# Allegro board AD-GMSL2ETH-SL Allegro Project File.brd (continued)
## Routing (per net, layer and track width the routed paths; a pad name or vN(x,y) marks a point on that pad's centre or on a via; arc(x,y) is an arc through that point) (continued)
VBUS_USB_DEBUG: length 13.2
  BOTTOM w0.229: D2.C 79.66,6.49
  BOTTOM w0.356: P10.1 80.9,5.25 79.66,6.49 79.05,6.49 77.57,7.98 R181.1 77.12,9.58 76.89,9.81 76.89,11.16 77.23,11.49 C260.1 C259.1 U23.10
VCC_IN: length 11.6
  TOP w0.305: U10.19 33.82,87.95
  TOP w0.483: R211.1 v1(36.4,110.59)
  TOP w0.508: 35.85,99.21 TP5.1 ; TP5.1 35.85,100.74 ; TP5.1 35.09,99.97 ; TP5.1 36.61,99.97
  L5_PWR w0.508: v1(36.4,110.59) 34.7,110.59 31.6,107.49 v1(30.45,107.49)
  vias: v1(28.77,50.91) v1(28.77,50.15) v1(29.54,50.91) v1(29.54,50.15) v1(36.78,88.58) v1(36.78,87.82) v1(37.54,88.58) v1(37.54,87.82)
VCC_IN_1: length 8.5
  TOP w0.508: v1(31.5,117.2) 31.5,116.51
  L6_PWR w0.508: v1(31.5,117.2) 31.5,115.56 28.88,112.94 v1(28.88,110.46)
VCCOEN_PL_M2C: length 59
  TOP w0.203: v1(61.65,55.75) 60.23,55.75 56.41,51.94 R51.1 50.06,51.94 49.81,51.69 U26.3 ; P3.A20 v2(80.13,92.06)
  BOTTOM w0.203: v1(61.65,55.75) 61.09,56.32 61.09,70.51 80.13,89.56 v2(80.13,92.06)
VCCOEN_PS_M2C: length 60.4
  TOP w0.203: U26.1 50.15,50.39 50.39,50.15 R50.1 57.11,50.15 v1(61.65,54.69) ; P3.A19 v2(79.5,92.06)
  BOTTOM w0.203: v1(61.65,54.69) 60.67,55.66 60.67,70.97 79.5,89.8 v2(79.5,92.06)
VDD_ANALOG: length 25.6
  TOP w0.203: U3.31 v2(96.61,110.19)
  TOP w0.305: U3.6 v2(96.61,101.83) ; U3.27 98.61,109.98 v1(98.36,110.22) 98.11,109.97 U3.28 ; v1(110.16,105.51) 109.79,105.89 R89.2 ; v1(101.17,109.18) 100.76,108.77 U3.24 ; U3.19 101.06,106.27 v1(101.32,106.53) 101.08,106.77 U3.20 ; R139.2 108.9,108.49 v1(109.73,109.32) ; v1(101.12,102.86) 100.7,103.27 U3.13 ; U3.45 v1(92.21,104.77) ; U3.9 98.11,101.87 v1(98.36,101.61) 98.61,101.86 U3.10 ; U3.41 92.91,106.77 v1(92.66,107.03) 92.91,107.27 U3.40 ; R88.2 v1(108.15,102.51)
  TOP w0.33: C98.1 v1(70.91,103.73) U14.5 U14.1
  TOP w0.356: v1(101.32,106.53) C97.1 ; v1(101.17,109.18) C102.1 ; v1(101.12,102.86) C95.1 ; C99.1 v1(98.36,101.61) ; v1(92.21,104.77) C101.1
  BOTTOM w0.305: R57.2 v1(104.88,100.15)
  BOTTOM w0.356: v1(98.36,110.22) 98.78,110.22 C94.1
  BOTTOM w0.406: v1(92.66,107.03) 92.66,107.03 C157.1 ; v2(96.61,101.83) C158.1
  BOTTOM w0.508: R55.2 v1(105.46,110.89)
  vias: v1(116.84,98.56) v1(116.84,97.8) v1(117.6,98.56) v1(117.6,97.8)
VDDOCXO_3V3: length 7.3
  TOP w0.406: Y4.4 C117.1 111.03,112.6 C112.1 E2.2
1PPS_IN: length 104.1
  TOP w0.483: R185.1 v1(75.74,106.72)
  TOP w0.508: D6.3 v1(20.25,56.41)
  TOP w0.61: D6.3 RT19.1
  BOTTOM w0.508: v1(75.74,106.72) 75.74,109.09 72.52,112.32 57.23,112.32 53.9,108.99 53.9,82.07 28.24,56.41 v1(20.25,56.41)
A_CAPVDD: length 18.9
  TOP w0.508: 114,80.56 v1(113.16,80.56) C9.1 ; C16.1 112.46,83.6 v1(112.8,83.94) 113.45,84.59
  TOP w0.61: C7.1 119.02,84.99 118.59,85.42 114.28,85.42 113.45,84.59 ; C15.1 117.93,82.61 115.88,80.56 114,80.56
  TOP w0.762: C7.1 C15.1
  BOTTOM w0.305: U1.8 112.85,84.21 112.85,83.99 v1(112.8,83.94) ; v1(113.16,80.56) 113.21,80.51 113.21,80.27 U1.20
A_CFG0: length 3.1
  TOP w0.356: v2(112.85,87.73) 113.51,88.39 R145.1
  BOTTOM w0.203: U1.4 112.62,86.82 112.62,87.5 v2(112.85,87.73)
A_CKAN/CKDN/A3A/D1A: length 81.7
  TOP w0.108: v2(84.66,35.56) 84.49,35.74 81.33,35.74 77.43,31.84 77.43,29.6 P5.D16
  L8_SIG w0.102: v7(101.48,78.79) 101.48,78.54 96.25,73.31 96.25,70.21 96.14,70.11 94.97,70.11 94.69,69.83 94.69,69.38 94.97,69.1 96.17,69.1 96.27,68.99 96.27,68.79 96.17,68.69 94.97,68.69 94.69,68.41 94.69,67.95 94.97,67.67 96.14,67.67 96.25,67.57 96.25,67.37 96.14,67.27 94.97,67.27 94.69,66.99 94.69,66.53 94.97,66.25 96.14,66.25 96.25,66.15 96.25,65.95 96.14,65.84 94.97,65.84 94.69,65.56 94.69,65.11 94.97,64.83 96.14,64.83 96.25,64.73 96.25,64.52 96.14,64.42 94.97,64.42 94.69,64.14 94.69,63.69 94.97,63.41 96.14,63.41 96.41,63.14 96.41,61.4 83.67,48.66 83.67,36.09 84.02,35.74 84.49,35.74 v2(84.66,35.56)
  BOTTOM w0.108: v7(101.48,78.79) 101.73,78.79 102.66,79.72 104.96,79.72 105.69,80.45 105.69,80.59 U1.40
A_CKAP/CKDP/A2C/D0C: length 81.8
  TOP w0.108: v2(84.66,36.22) 84.48,36.04 81.2,36.04 77.12,31.97 77.12,29.6 P5.D15
  L8_SIG w0.102: v2(84.66,36.22) 84.48,36.04 84.15,36.04 83.97,36.22 83.97,37.53 84.07,37.63 84.15,37.63 84.25,37.74 84.25,37.94 84.15,38.04 84.07,38.04 83.97,38.14 83.97,48.53 96.71,61.27 96.71,63.27 96.27,63.71 95.09,63.71 94.99,63.81 94.99,64.02 95.09,64.12 96.27,64.12 96.55,64.4 96.55,64.85 96.27,65.13 95.09,65.13 94.99,65.23 94.99,65.44 95.09,65.54 96.27,65.54 96.55,65.82 96.55,66.28 96.27,66.56 95.09,66.56 94.99,66.66 94.99,66.86 95.09,66.96 96.27,66.96 96.55,67.24 96.55,67.7 96.27,67.98 95.09,67.98 94.99,68.08 94.99,68.28 95.09,68.38 96.3,68.38 96.58,68.66 96.58,69.12 96.3,69.4 95.09,69.4 94.99,69.5 94.99,69.7 95.09,69.81 96.27,69.81 96.55,70.09 96.55,73.18 101.69,78.33 v7(101.95,78.33)
  BOTTOM w0.108: U1.39 106.05,80.24 105.91,80.24 105.09,79.42 102.79,79.42 101.95,78.58 v7(101.95,78.33)
A_CKBN/CKEN/B1A/E1A: length 109.5
  TOP w0.108: v2(75.37,26.41) P5.B13
  L8_SIG w0.102: v2(75.37,26.41) 75.21,26.25 75.21,25.86 74.82,25.47 73.79,25.47 73.33,25.93 73.33,30.43 75.44,32.54 78.23,32.54 78.33,32.64 78.33,32.86 78.23,32.96 77.16,32.96 76.88,33.24 76.88,33.7 77.16,33.98 78.38,33.98 78.48,34.08 78.48,34.27 78.37,34.38 77.16,34.38 76.88,34.66 76.88,35.12 77.16,35.4 78.38,35.4 78.48,35.5 78.48,35.7 78.37,35.81 77.16,35.81 76.88,36.09 76.88,36.54 77.16,36.82 78.38,36.82 78.48,36.92 78.48,37.12 78.37,37.23 77.16,37.23 76.88,37.51 76.88,37.96 77.16,38.24 78.38,38.24 78.48,38.35 78.48,38.54 78.37,38.65 77.16,38.65 76.88,38.93 76.88,39.39 77.16,39.67 78.38,39.67 78.48,39.77 78.48,39.96 78.37,40.07 77.16,40.07 76.88,40.35 76.88,40.81 77.16,41.09 78.38,41.09 78.48,41.19 78.48,41.39 78.37,41.5 77.16,41.5 76.88,41.78 76.88,42.23 77.16,42.51 78.38,42.51 78.48,42.61 78.48,42.81 78.37,42.92 77.16,42.92 76.88,43.2 76.88,43.65 77.16,43.93 78.38,43.93 78.48,44.04 78.48,44.23 78.37,44.34 77.16,44.34 76.88,44.62 76.88,45.08 77.16,45.36 78.38,45.36 78.48,45.46 78.48,45.65 78.37,45.76 77.26,45.76 76.98,46.04 76.98,46.49 77.27,46.78 78.38,46.78 78.48,46.88 78.48,63.23 100.71,85.46 103.25,85.46 v7(103.43,85.64)
  BOTTOM w0.108: v7(103.43,85.64) 103.6,85.46 104.35,85.46 105.61,84.19 105.75,84.19 U1.46
A_CKBP/CKEP/B0C/E0C: length 109.3
  TOP w0.108: v2(74.74,26.41) P5.B12
  L8_SIG w0.102: v2(74.74,26.41) 74.9,26.25 74.9,25.99 74.69,25.78 73.91,25.78 73.63,26.06 73.63,27.21 73.73,27.31 74.01,27.31 74.11,27.41 74.11,27.61 74.01,27.71 73.73,27.71 73.63,27.82 73.63,28.02 73.73,28.12 74.01,28.12 74.11,28.22 74.11,28.43 74.01,28.53 73.73,28.53 73.63,28.63 73.63,30.3 75.56,32.23 78.35,32.23 78.63,32.51 78.63,32.99 78.35,33.27 77.29,33.27 77.19,33.37 77.19,33.57 77.29,33.67 78.51,33.67 78.78,33.95 78.78,34.4 78.5,34.69 77.29,34.69 77.19,34.79 77.19,34.99 77.29,35.1 78.51,35.1 78.78,35.37 78.78,35.82 78.5,36.11 77.29,36.11 77.19,36.21 77.19,36.42 77.29,36.52 78.51,36.52 78.78,36.79 78.78,37.25 78.5,37.53 77.29,37.53 77.19,37.64 77.19,37.84 77.29,37.94 78.51,37.94 78.78,38.21 78.78,38.67 78.5,38.96 77.29,38.96 77.19,39.06 77.19,39.26 77.29,39.36 78.51,39.36 78.78,39.63 78.78,40.09 78.5,40.38 77.29,40.38 77.19,40.48 77.19,40.68 77.29,40.78 78.51,40.78 78.78,41.06 78.78,41.51 78.5,41.8 77.29,41.8 77.19,41.9 77.19,42.11 77.29,42.21 78.51,42.21 78.78,42.48 78.78,42.94 78.5,43.22 77.29,43.22 77.19,43.32 77.19,43.53 77.29,43.63 78.51,43.63 78.78,43.9 78.78,44.36 78.5,44.65 77.29,44.65 77.19,44.75 77.19,44.95 77.29,45.05 78.51,45.05 78.78,45.32 78.78,45.78 78.5,46.07 77.39,46.07 77.29,46.17 77.29,46.36 77.4,46.47 78.5,46.47 78.78,46.75 78.78,63.1 100.84,85.16 103.25,85.16 v7(103.43,84.98)
  BOTTOM w0.108: U1.45 105.4,83.84 105.4,83.98 104.22,85.15 103.6,85.15 v7(103.43,84.98)
A_DA0N/DC0N/A0B/C0B: length 84.6
  TOP w0.108: v2(91.81,36.18) 91.63,36.36 88.37,36.36 87.03,37.7 80.41,37.7 75.53,32.82 75.53,29.6 P5.D13
  L8_SIG w0.102: v7(107.21,77.45) 107.02,77.26 106.31,77.26 105.7,76.66 105.7,67.25 105.98,66.97 107.63,66.97 107.73,66.86 107.73,66.66 107.63,66.56 105.98,66.56 105.7,66.28 105.7,65.82 105.98,65.54 107.63,65.54 107.73,65.44 107.73,65.24 107.63,65.14 105.98,65.14 105.7,64.86 105.7,64.4 105.98,64.12 107.63,64.12 107.73,64.02 107.73,63.82 107.63,63.71 105.98,63.71 105.7,63.43 105.7,59.48 90.65,44.43 90.65,36.97 91.26,36.36 91.63,36.36 91.63,36.36 v2(91.81,36.18)
  BOTTOM w0.108: v7(107.21,77.45) 107.38,77.27 108.16,77.27 108.53,77.63 108.53,77.77 U1.32
A_DA0P/DC0P/A0A/C0A: length 85.1
  TOP w0.108: P5.D12 75.22,29.6 75.22,32.94 80.28,38.01 87.16,38.01 88.5,36.66 91.63,36.66 v2(91.81,36.84)
  L8_SIG w0.102: v7(107.21,76.78) 107.03,76.96 106.43,76.96 106.01,76.53 106.01,67.37 106.11,67.27 107.76,67.27 108.04,66.99 108.04,66.53 107.76,66.25 106.11,66.25 106.01,66.15 106.01,65.95 106.11,65.85 107.76,65.85 108.04,65.57 108.04,65.11 107.76,64.83 106.11,64.83 106.01,64.73 106.01,64.53 106.11,64.43 107.76,64.43 108.04,64.15 108.04,63.69 107.76,63.41 106.11,63.41 106.01,63.31 106.01,59.35 90.95,44.3 90.95,39.12 91.06,39.01 91.35,39.01 91.45,38.91 91.45,38.71 91.35,38.61 91.06,38.61 90.95,38.51 90.95,37.1 91.39,36.66 91.63,36.66 v2(91.81,36.84)
  BOTTOM w0.108: U1.31 108.88,77.42 108.74,77.42 108.29,76.96 107.38,76.96 v7(107.21,76.78)
A_DA1N/DC1N/A1C/C1C: length 76
  TOP w0.108: P5.C18 v2(79.18,28.95)
  L8_SIG w0.102: v2(79.18,28.95) 79.02,28.79 79.02,27.77 79.72,27.07 79.72,25.61 80.04,25.29 80.18,25.29 80.33,25.44 80.49,25.44 80.63,25.31 80.63,25.16 80.47,25 80.47,24.86 80.9,24.42 86.5,24.42 88.26,26.19 88.26,46.24 103.06,61.03 103.06,74.99 103.98,75.92 v7(103.98,76.17)
  BOTTOM w0.108: v7(103.98,76.17) 104.23,76.17 107.11,79.05 107.11,79.18 U1.36
A_DA1P/DC1P/A1B/C1B: length 76.2
  TOP w0.108: P5.C17 v2(78.55,28.95)
  L8_SIG w0.102: v7(104.45,75.7) 104.2,75.7 103.36,74.86 103.36,60.9 88.57,46.11 88.57,26.06 86.63,24.12 80.78,24.12 79.41,25.48 79.41,26.95 78.71,27.65 78.71,28.78 v2(78.55,28.95)
  BOTTOM w0.108: v7(104.45,75.7) 104.45,75.95 107.31,78.82 107.45,78.82 U1.35
A_DA2N/DD0N/A2B/D0B: length 77
  TOP w0.108: v2(82.99,27.37) P5.B25
  L8_SIG w0.102: v7(103.56,78.32) 103.56,78.07 99.78,74.29 99.78,60.64 98.29,59.15 98.15,59.15 97.62,59.68 97.22,59.68 96.9,59.36 96.9,58.96 97.43,58.43 97.43,58.29 97.29,58.14 97.14,58.14 96.61,58.68 96.21,58.68 95.89,58.36 95.89,57.96 96.43,57.42 96.43,57.28 96.28,57.14 96.14,57.14 95.6,57.67 95.21,57.67 94.89,57.35 94.89,56.95 95.42,56.42 95.42,56.28 95.28,56.13 95.13,56.13 94.6,56.67 94.2,56.67 93.88,56.34 93.88,55.95 94.41,55.41 94.41,55.27 94.27,55.13 94.13,55.13 93.59,55.66 93.2,55.66 92.87,55.34 92.87,54.94 93.41,54.41 93.41,54.26 93.26,54.12 93.12,54.12 92.59,54.65 92.19,54.65 91.87,54.33 91.87,53.94 92.4,53.4 92.4,53.26 86.36,47.22 86.36,28.7 84.86,27.2 84.32,27.2 84.22,27.3 84.22,27.51 84.11,27.61 83.91,27.61 83.81,27.51 83.81,27.3 83.71,27.2 83.17,27.2 v2(82.99,27.37)
  BOTTOM w0.108: U1.38 106.4,79.89 106.4,79.75 105.37,78.72 104.21,78.72 103.81,78.32 v7(103.56,78.32)
A_DA2P/DD0P/A2A/D0A: length 76.9
  TOP w0.108: v2(82.99,26.41) P5.B24
  L8_SIG w0.102: v2(82.99,26.41) 82.99,26.72 83.17,26.89 84.98,26.89 86.66,28.57 86.66,47.09 92.71,53.13 92.71,53.53 92.17,54.06 92.17,54.21 92.32,54.35 92.46,54.35 92.99,53.81 93.39,53.81 93.71,54.14 93.71,54.53 93.18,55.07 93.18,55.21 93.32,55.35 93.47,55.35 94,54.82 94.4,54.82 94.72,55.14 94.72,55.54 94.18,56.07 94.18,56.22 94.33,56.36 94.47,56.36 95.01,55.83 95.4,55.83 95.72,56.15 95.72,56.54 95.19,57.08 95.19,57.22 95.33,57.37 95.48,57.37 96.01,56.83 96.41,56.83 96.73,57.15 96.73,57.55 96.2,58.09 96.2,58.23 96.34,58.37 96.48,58.37 97.02,57.84 97.41,57.84 97.74,58.16 97.74,58.56 97.2,59.09 97.2,59.23 97.35,59.38 97.49,59.38 98.02,58.84 98.42,58.84 100.08,60.51 100.08,74.16 103.77,77.85 v7(104.02,77.85)
  BOTTOM w0.108: v7(104.02,77.85) 104.02,78.1 104.34,78.41 105.5,78.41 106.61,79.53 106.75,79.53 U1.37
A_DA3N/DD1N/A3C/D1C: length 78.3
  TOP w0.108: v2(83.49,33.7) 83.31,33.88 82.71,33.88 81.24,32.41 81.24,29.6 P5.D22
  L8_SIG w0.102: v2(83.49,33.7) 83.31,33.88 82.84,33.88 81.94,34.78 81.94,51 83.43,52.5 83.83,52.5 84.55,51.79 84.69,51.79 84.83,51.93 84.83,52.07 84.12,52.79 84.12,53.19 84.44,53.51 84.84,53.51 85.55,52.79 85.7,52.79 85.84,52.94 85.84,53.08 85.12,53.79 85.12,54.19 85.45,54.51 85.84,54.51 86.56,53.8 86.7,53.8 86.85,53.94 86.85,54.08 86.13,54.8 86.13,55.2 86.45,55.52 86.85,55.52 87.56,54.8 87.71,54.8 87.85,54.95 87.85,55.09 87.14,55.81 87.14,56.2 87.46,56.53 87.85,56.53 88.57,55.81 88.71,55.81 88.86,55.95 88.86,56.1 88.29,56.67 88.29,57.06 92.79,61.56 92.79,72.53 101.08,80.82 101.64,80.82 v7(101.82,81)
  BOTTOM w0.108: v7(101.82,81) 101.99,80.82 104.64,80.82 104.98,81.16 104.98,81.29 U1.42
A_DA3P/DD1P/A3B/D1B: length 78.5
  TOP w0.108: v2(83.49,34.36) 83.31,34.19 82.59,34.19 80.93,32.53 80.93,29.6 P5.D21
  L8_SIG w0.102: v7(101.82,80.34) 101.64,80.52 101.21,80.52 93.09,72.4 93.09,61.44 88.59,56.94 88.59,56.79 89.16,56.22 89.16,55.83 88.84,55.5 88.44,55.5 87.73,56.22 87.58,56.22 87.44,56.08 87.44,55.93 88.16,55.22 88.16,54.82 87.83,54.5 87.44,54.5 86.72,55.21 86.58,55.21 86.43,55.07 86.43,54.93 87.15,54.21 87.15,53.82 86.83,53.49 86.43,53.49 85.72,54.21 85.57,54.21 85.43,54.06 85.43,53.92 86.14,53.21 86.14,52.81 85.82,52.49 85.43,52.49 84.71,53.2 84.57,53.2 84.42,53.06 84.42,52.92 85.14,52.2 85.14,51.8 84.82,51.48 84.42,51.48 83.7,52.2 83.56,52.2 82.24,50.88 82.24,35.82 82.34,35.72 82.49,35.72 82.59,35.62 82.59,35.41 82.49,35.31 82.34,35.31 82.24,35.21 82.24,34.91 82.96,34.19 83.31,34.19 v2(83.49,34.36)
  BOTTOM w0.108: U1.41 105.32,80.92 105.18,80.92 104.77,80.52 101.99,80.52 v7(101.82,80.34)
A_DB0N/DE0N/B0B/E0B: length 108.8
  TOP w0.108: P5.B22 v2(81.09,27.37)
  L8_SIG w0.102: v2(81.09,27.37) 81.36,27.37 81.58,27.59 81.58,30.54 80.21,31.91 80.21,32.58 80.11,32.68 80.03,32.68 79.93,32.78 79.93,32.99 80.03,33.09 80.11,33.09 80.21,33.19 80.21,53.69 80.49,53.97 82.41,53.97 82.51,54.08 82.51,54.28 82.41,54.38 80.49,54.38 80.21,54.66 80.21,55.12 80.49,55.4 82.41,55.4 82.51,55.5 82.51,55.7 82.41,55.8 80.49,55.8 80.21,56.08 80.21,56.54 80.49,56.82 82.41,56.82 82.51,56.92 82.51,57.12 82.41,57.23 80.49,57.23 80.21,57.51 80.21,57.96 80.49,58.24 82.41,58.24 82.51,58.34 82.51,58.55 82.41,58.65 80.54,58.65 80.26,58.93 80.26,59.4 80.54,59.68 81.86,59.68 81.97,59.78 81.97,60.97 82.86,61.87 82.86,62.01 82.19,62.68 82.19,63.07 82.51,63.4 82.91,63.4 83.7,62.61 83.84,62.61 83.98,62.75 83.98,62.89 83.2,63.68 83.2,64.08 83.52,64.4 83.91,64.4 84.7,63.61 84.85,63.61 84.99,63.76 84.99,63.9 84.2,64.69 84.2,65.09 84.52,65.41 84.92,65.41 85.71,64.62 85.85,64.62 86,64.76 86,64.91 85.21,65.7 85.21,66.09 85.53,66.41 85.93,66.41 86.95,65.39 87.1,65.39 87.24,65.53 87.24,65.67 86.21,66.7 86.21,67.1 86.54,67.42 86.96,67.42 88.03,66.35 88.18,66.35 88.31,66.48 88.31,66.62 87.22,67.71 87.22,68.1 87.54,68.43 87.94,68.43 88.73,67.64 88.87,67.64 89.01,67.78 89.01,67.92 88.22,68.71 88.22,69.11 88.55,69.43 88.94,69.43 89.73,68.64 89.88,68.64 90.09,68.85 90.09,68.99 89.42,69.67 89.42,71.65 101.42,83.65 102.53,83.65 v7(102.7,83.83)
  BOTTOM w0.108: U1.44 105.3,83.24 105.16,83.24 104.74,83.65 102.88,83.65 v7(102.7,83.83)
A_DB0P/DE0P/B0A/E0A: length 108.6
  TOP w0.108: v2(81.09,26.41) P5.B21
  L8_SIG w0.102: v2(81.09,26.41) 81.09,26.41 81.09,26.67 81.88,27.46 81.88,30.66 80.52,32.03 80.52,53.57 80.62,53.67 82.54,53.67 82.82,53.95 82.82,54.41 82.54,54.69 80.62,54.69 80.52,54.79 80.52,54.99 80.62,55.09 82.54,55.09 82.82,55.37 82.82,55.83 82.54,56.11 80.62,56.11 80.52,56.21 80.52,56.41 80.62,56.51 82.54,56.51 82.82,56.79 82.82,57.25 82.54,57.53 80.62,57.53 80.52,57.63 80.52,57.84 80.62,57.94 82.54,57.94 82.82,58.22 82.82,58.67 82.54,58.95 80.67,58.95 80.57,59.05 80.57,59.27 80.67,59.38 81.99,59.38 82.27,59.66 82.27,60.85 83.16,61.74 83.16,62.14 82.49,62.8 82.49,62.95 82.64,63.09 82.78,63.09 83.57,62.3 83.97,62.3 84.29,62.62 84.29,63.02 83.5,63.81 83.5,63.95 83.64,64.1 83.79,64.1 84.58,63.31 84.97,63.31 85.3,63.63 85.3,64.03 84.51,64.82 84.51,64.96 84.65,65.1 84.79,65.1 85.58,64.31 85.98,64.31 86.3,64.64 86.3,65.03 85.51,65.82 85.51,65.96 85.66,66.11 85.8,66.11 86.83,65.08 87.22,65.08 87.55,65.4 87.55,65.8 86.52,66.83 86.52,66.97 86.66,67.11 86.84,67.11 87.91,66.04 88.3,66.04 88.61,66.35 88.61,66.75 87.52,67.83 87.52,67.98 87.67,68.12 87.81,68.12 88.6,67.33 89,67.33 89.32,67.65 89.32,68.05 88.53,68.84 88.53,68.98 88.67,69.13 88.82,69.13 89.61,68.34 90.01,68.34 90.4,68.72 90.4,69.12 89.72,69.79 89.72,71.53 101.54,83.35 102.53,83.35 v7(102.7,83.17)
  BOTTOM w0.108: v7(102.7,83.17) 102.88,83.35 104.61,83.35 104.94,83.02 104.94,82.88 U1.43
A_DB1N/DE1N/B1C/E1C: length 113.2
  TOP w0.108: P5.A18 78.7,25.77 78.7,23.79 78.14,23.23 76.56,23.23 75.71,24.08 75.34,24.08 75.18,23.93 v2(75.14,23.93)
  L8_SIG w0.102: v7(102.44,87.4) 102.26,87.22 99.6,87.22 74.8,62.42 74.8,60.36 75.09,60.07 76.42,60.07 76.53,59.96 76.53,59.76 76.42,59.66 75.12,59.66 74.84,59.38 74.84,58.92 75.12,58.64 76.42,58.64 76.53,58.54 76.53,58.34 76.42,58.24 75.32,58.24 75.04,57.96 75.04,57.5 75.32,57.22 76.42,57.22 76.53,57.12 76.53,56.92 76.42,56.81 75.32,56.81 75.04,56.53 75.04,56.08 75.32,55.8 76.42,55.8 76.53,55.7 76.53,55.49 76.42,55.39 75.32,55.39 75.04,55.11 75.04,54.66 75.32,54.38 76.42,54.38 76.53,54.27 76.53,54.07 76.42,53.97 75.32,53.97 75.04,53.69 75.04,53.23 75.32,52.95 76.42,52.95 76.53,52.85 76.53,52.65 76.42,52.55 75.32,52.55 75.04,52.27 75.04,51.81 75.32,51.53 76.42,51.53 76.53,51.43 76.53,51.23 76.42,51.13 75.32,51.13 75.04,50.84 75.04,50.39 75.32,50.11 76.42,50.11 76.53,50.01 76.53,49.8 76.42,49.7 75.32,49.7 75.04,49.42 75.04,35.09 72.05,32.1 72.05,25.39 73.35,24.08 74.73,24.08 74.88,23.93 v2(75.14,23.93)
  BOTTOM w0.108: v7(102.44,87.4) 102.62,87.22 104,87.22 106.32,84.9 106.46,84.9 U1.48
A_DB1P/DE1P/B1B/E1B: length 113
  TOP w0.108: v2(75.14,24.54) 75.18,24.54 75.34,24.39 75.84,24.39 76.69,23.54 78.01,23.54 78.4,23.92 78.4,25.76 P5.A17
  L8_SIG w0.102: v2(75.14,24.54) 74.88,24.54 74.73,24.39 73.48,24.39 72.36,25.51 72.36,31.98 72.95,32.57 73.09,32.57 73.33,32.34 73.47,32.34 73.62,32.48 73.62,32.62 73.38,32.86 73.38,33 73.52,33.15 73.67,33.15 73.88,32.93 74.02,32.93 74.17,33.08 74.17,33.22 73.96,33.43 73.96,33.58 75.34,34.96 75.34,49.3 75.44,49.4 76.55,49.4 76.83,49.68 76.83,50.13 76.55,50.41 75.44,50.41 75.34,50.52 75.34,50.72 75.44,50.82 76.55,50.82 76.83,51.1 76.83,51.56 76.55,51.84 75.44,51.84 75.34,51.94 75.34,52.14 75.44,52.24 76.55,52.24 76.83,52.52 76.83,52.98 76.55,53.26 75.44,53.26 75.34,53.36 75.34,53.56 75.44,53.67 76.55,53.67 76.83,53.95 76.83,54.4 76.55,54.68 75.44,54.68 75.34,54.78 75.34,54.99 75.44,55.09 76.55,55.09 76.83,55.37 76.83,55.82 76.55,56.1 75.44,56.1 75.34,56.21 75.34,56.41 75.44,56.51 76.55,56.51 76.83,56.79 76.83,57.25 76.55,57.53 75.44,57.53 75.34,57.63 75.34,57.83 75.44,57.93 76.55,57.93 76.83,58.21 76.83,58.67 76.55,58.95 75.24,58.95 75.14,59.05 75.14,59.25 75.24,59.35 76.55,59.35 76.83,59.63 76.83,60.09 76.55,60.37 75.22,60.37 75.1,60.49 75.1,62.29 99.73,86.92 102.26,86.92 v7(102.44,86.74)
  BOTTOM w0.108: v7(102.44,86.74) 102.62,86.91 103.87,86.91 106.1,84.69 106.1,84.55 U1.47
A_DB2N/DF0N/B2B/F0B: length 109.4
  TOP w0.108: P5.C21 v2(80.45,28.95)
  L8_SIG w0.102: v2(80.45,28.95) 80.64,29.14 80.64,29.85 79.91,30.58 76.03,30.58 75.55,30.1 75.55,28.34 77.03,26.87 77.03,23.94 75.73,22.65 72.84,22.65 70.78,24.7 70.78,33.3 71.22,33.74 71.22,33.88 71.1,34 71.1,34.14 71.25,34.29 71.39,34.29 71.51,34.17 71.65,34.17 72.88,35.4 72.88,37.54 72.16,38.26 72.16,62.54 98.58,88.96 103.68,88.96 104.08,88.56 v7(104.33,88.56)
  BOTTOM w0.108: U1.50 107.16,85.61 107.03,85.61 104.33,88.31 v7(104.33,88.56)
A_DB2P/DF0P/B2A/F0A: length 109.2
  TOP w0.108: v2(80.45,27.99) P5.C20
  L8_SIG w0.102: v7(103.86,88.09) 103.86,88.35 103.56,88.65 98.7,88.65 72.46,62.42 72.46,38.39 73.19,37.67 73.19,35.27 71.08,33.17 71.08,24.83 72.96,22.95 75.6,22.95 76.72,24.07 76.72,26.74 75.25,28.21 75.25,30.23 75.91,30.89 80.03,30.89 80.95,29.97 80.95,28.87 80.45,28.37 v2(80.45,27.99)
  BOTTOM w0.108: v7(103.86,88.09) 104.11,88.09 106.81,85.4 106.81,85.26 U1.49
A_DB3N/DF1N/B3C/F1C: length 109.2
  TOP w0.108: P5.C15 v2(77.28,28.95)
  L8_SIG w0.102: v7(106.2,89.22) 105.94,89.22 104.59,90.57 97.52,90.57 69.49,62.54 69.49,24.06 71.83,21.72 76.78,21.72 78.64,23.57 78.64,26.68 77.11,28.21 77.11,28.79 v2(77.28,28.95)
  BOTTOM w0.108: U1.54 108.87,86.74 108.73,86.74 108.37,87.1 108.06,87.1 106.2,88.97 v7(106.2,89.22)
A_DB3P/DF1P/B3B/F1B: length 109.2
  TOP w0.108: P5.C14 v2(76.64,28.95)
  L8_SIG w0.102: v2(76.64,28.95) 76.81,28.79 76.81,28.08 78.34,26.55 78.34,25.56 78.23,25.46 77.88,25.46 77.78,25.36 77.78,25.16 77.88,25.05 78.23,25.05 78.34,24.95 78.34,24.75 78.23,24.65 77.88,24.65 77.78,24.55 77.78,24.34 77.88,24.24 78.23,24.24 78.34,24.14 78.34,23.7 76.66,22.02 71.96,22.02 69.8,24.18 69.8,62.42 97.64,90.27 104.47,90.27 105.73,89 v7(105.73,88.75)
  BOTTOM w0.108: v7(105.73,88.75) 105.98,88.75 107.94,86.8 108.24,86.8 108.51,86.52 108.51,86.38 U1.53
A_GMSL-PWDNB: length 78.1
  TOP w0.203: v2(95.06,27.37) P5.B44
  TOP w0.356: v1(112.26,90.73) 113.51,90.73 R154.1
  L3_SIG w0.356: v2(115.04,84.28) 115.04,87.96 v1(112.26,90.73)
  L8_SIG w0.203: v2(95.06,27.37) 93.51,28.92 93.51,32.04 95.48,34.01 95.48,44.92 110.49,59.93 110.49,68.63 116.48,74.62 116.48,82.07 115.04,83.52 v2(115.04,84.28)
  BOTTOM w0.203: U1.11 v2(115.04,84.28)
A_MFP0/LMN0/FSYNC: length 81.3
  TOP w0.203: v2(96.96,25.45) P5.A46
  L8_SIG w0.203: v2(111.51,89) 111.79,89.28 113.41,89.28 114.58,88.11 114.58,83.39 116.08,81.89 116.08,74.79 110.08,68.8 110.08,60.1 95.07,45.09 95.07,34.18 93.1,32.21 93.1,28.54 96.19,25.45 v2(96.96,25.45)
  BOTTOM w0.203: v2(111.51,89) 111.25,88.75 111.25,87.57 U1.1
A_MFP1/LMN1/VS0/DE0/HS0: length 81.8
  TOP w0.203: v2(97.6,25.45) P5.A47
  L8_SIG w0.203: v2(111.96,88.57) 112.24,88.85 113.18,88.85 114.15,87.88 114.15,83.24 115.67,81.71 115.67,74.98 109.66,68.97 109.66,60.26 94.67,45.26 94.67,34.35 92.69,32.37 92.69,28.36 96.08,24.97 97.41,24.97 97.6,25.16 v2(97.6,25.45)
  BOTTOM w0.203: v2(111.96,88.57) 111.71,88.32 111.71,87.32 U1.2
A_MFP2/LMN2: length 82.1
  TOP w0.203: v2(98.23,25.45) P5.A48
  L8_SIG w0.203: v2(112.4,88.14) 112.65,88.39 113.06,88.39 113.73,87.72 113.73,83.06 115.27,81.53 115.27,75.15 109.26,69.14 109.26,60.42 94.26,45.43 94.26,34.52 92.28,32.54 92.28,28.19 95.91,24.56 97.69,24.56 98.23,25.11 v2(98.23,25.45)
  BOTTOM w0.203: v2(112.4,88.14) 112.17,87.91 112.17,87.07 U1.3
A_MFP3/LMN3/VS1/DE1/HS1: length 69.3
  TOP w0.203: v2(95.69,27.37) P5.B45
  L8_SIG w0.203: v2(95.69,27.37) 95.69,27.4 93.91,29.17 93.91,31.87 95.88,33.84 95.88,44.75 110.9,59.77 110.9,68.46 116.89,74.45 116.89,82.24 115.57,83.56 v2(115.57,84.1)
  BOTTOM w0.203: v2(115.57,84.1) U1.12
A_MFP4/LOCK: length 70.7
  TOP w0.203: v2(96.33,27.37) P5.B46
  L8_SIG w0.203: v2(116.53,84.36) 116.13,83.96 116.13,83.58 117.3,82.41 117.3,74.29 111.3,68.29 111.3,59.6 96.29,44.59 96.29,33.67 94.32,31.7 94.32,29.39 96.33,27.38 v2(96.33,27.37)
  BOTTOM w0.203: v2(116.53,84.36) U1.13
A_MFP5/ERRB: length 69.9
  TOP w0.203: v2(95.7,29) 96.3,29 P5.C46
  L8_SIG w0.203: v2(116.62,83.74) 118.55,81.8 118.55,74.54 118.08,74.07 118.08,70.08 117.4,69.39 114.13,69.39 112.55,67.81 112.55,59.12 97.51,44.08 97.51,32.26 96.24,30.99 96.24,29.54 v2(95.7,29)
  BOTTOM w0.203: v2(116.62,83.74) U1.14
A_MFP6/CFG1: length 69.8
  TOP w0.203: P5.C47 97.28,28.12 97.05,27.89 v2(96.61,27.89)
  TOP w0.305: R151.1 119.51,71.18 v2(119.51,70.03)
  L8_SIG w0.203: v2(96.61,27.89) 96.61,30.77 97.92,32.08 97.92,43.91 112.95,58.95 112.95,67.64 114.3,68.99 117.58,68.99 118.59,70 119.47,70 v2(119.51,70.03)
  BOTTOM w0.203: v2(119.51,70.03) 118.88,69.41 117.25,69.41 113.23,73.43 113.23,76.72 113.06,76.89 113.06,76.89 112.87,77.08 112.87,77.08 111.87,78.08 U1.25
A_MFP7: length 52.5
  TOP w0.203: v2(95.69,29.91) P5.D45 ; R125.2 v2(117.57,70.31)
  L8_SIG w0.203: v2(95.69,29.91) 95.69,31.91 97.1,33.32 97.1,44.25 112.12,59.26 112.12,67.95 113.96,69.8 117.06,69.8 v2(117.57,70.31)
A_MFP7/SDA1_RX1: length 12.1
  TOP w0.203: v2(112.6,75.34) 112.6,74.85 116.67,70.78 R125.1 R167.2 116.67,68.38 116.56,68.27 U20.2
  BOTTOM w0.203: U1.26 112.6,76.64 v2(112.6,75.34)
A_MFP8: length 50.6
  TOP w0.203: v2(95.06,29.91) P5.D44 ; R126.2 v2(115.04,70.31)
  L8_SIG w0.203: v2(95.06,29.91) 95.06,31.85 96.7,33.49 96.7,44.42 111.71,59.43 111.71,68.12 113.89,70.31 v2(115.04,70.31)
A_MFP8/SCL1_TX1: length 11.6
  TOP w0.203: v2(111.99,75.34) 111.99,74.68 115.94,70.73 R126.1 R166.2 115.94,68.38 116.06,68.27 U20.3
  BOTTOM w0.203: v2(111.99,75.34) 111.99,76.54 U1.27
A_SCL: length 46.6
  TOP w0.203: U19.8 138.85,59.12 v2(139.04,59.31) 140.93,59.31 R129.2
  L3_SIG w0.203: v2(139.04,59.31) 139.55,58.8 139.55,58.23 139.25,57.94 134.63,57.94 133.78,58.79 133.78,60.66 130.33,64.11 126.62,64.11 124.74,65.99 124.74,71.76 120.64,75.87 111.06,75.87 v2(111.05,75.87)
  BOTTOM w0.203: U1.29 v2(111.05,75.87)
A_SDA: length 43.6
  TOP w0.203: U19.7 138.86,58.62 v2(139.04,58.45) R134.2
  L3_SIG w0.203: v2(111.5,76.32) 121.06,76.32 125.28,72.1 125.28,66.13 126.85,64.57 130.52,64.57 134.24,60.85 134.24,58.98 134.77,58.45 v2(139.04,58.45)
  BOTTOM w0.203: U1.28 v2(111.5,76.32)
A_SIOAN: length 2
  BOTTOM w0.127: C41.1 114.18,77.88 U1.22
A_SIOAP: length 2
  BOTTOM w0.127: U1.23 113.83,77.53 C45.2
A_SIOBN: length 2
  BOTTOM w0.127: C42.1 115.25,78.94 U1.19
A_SIOBP: length 2
  BOTTOM w0.127: C46.2 115.62,79.28 U1.18
A_SIOCN: length 2
  BOTTOM w0.127: U1.9 114.92,85.58 C43.1
A_SIOCP: length 2
  BOTTOM w0.127: U1.10 114.33,84.28 114.33,84.28 114.65,84.61 114.66,84.61 115.25,85.2 C47.2
A_SIODN: length 2
  BOTTOM w0.127: U1.6 113.84,86.62 C44.1
A_SIODP: length 2
  BOTTOM w0.127: C48.2 113.5,86.99 U1.5
A_VDD18: length 27.8
  TOP w0.483: v1(112.21,84.52) 111.88,84.18 C6.1 C5.1 ; v1(112.57,79.98) C18.1 C19.1
  TOP w0.508: 112.21,85.69 C5.1 ; v1(112.57,79.98) 113.14,79.41
  TOP w0.61: 113.14,79.41 117.01,79.41 117.83,80.23 C152.1 ; R1.2 C4.1 113.89,87.37 112.21,85.69
  L3_SIG w0.508: v1(112.57,79.98) 112.24,80.31 112.24,80.72 113.24,81.72 113.24,82.44 111.9,83.78 111.9,84.21 112.21,84.52 v1(112.21,84.52)
  BOTTOM w0.305: v1(112.57,79.98) 112.62,79.93 112.85,79.93 U1.21 ; U1.7 112.5,84.57 112.26,84.57 v1(112.21,84.52)
A_VPOC_1: length 4.7
  TOP w0.305: 139.7,94.95 140.1,95.34 U12.6
  TOP w0.508: R189.1 138.77,93.46 C28.1 139.7,94.39 139.7,94.95
A_VPOC_2: length 4.9
  TOP w0.305: U12.20 140.1,100.1 139.7,100.5
  TOP w0.508: R192.1 137.83,100.28 C27.1 139.7,101.06 139.7,100.5
A_VPOC_3: length 5.2
  TOP w0.305: 141,94.95 140.6,95.34 U12.7
  TOP w0.508: R193.1 142.54,93.84 C29.1 141,94.39 141,94.95
A_VPOC_4: length 4.5
  TOP w0.305: U12.19 140.6,100.1 140.99,100.5
  TOP w0.508: R194.1 143.7,101.6 C30.1 140.99,101.06 140.99,100.5
A_VTERM: length 1
  BOTTOM w0.305: 109.09,76.61 109.09,76.92 U1.30
AD9545_OUT0B_N: length 47.1
  TOP w0.203: P3.C13 v2(75.69,94.6) ; R91.2 108.55,103.2 109.49,102.26 110.38,102.26 111.12,101.52 111.12,99.54 109.1,97.51 106.76,97.51 106.6,97.36 v1(106.27,97.36)
  BOTTOM w0.203: v1(106.27,97.36) 76.97,97.36 75.56,95.95 75.56,95.05 75.69,94.92 v2(75.69,94.6)
AD9545_OUT0B_P: length 46.6
  TOP w0.203: v1(106.27,98.07) 106.61,98.07 106.76,97.92 108.93,97.92 110.72,99.71 110.72,101.35 110.21,101.85 109.49,101.85 108.55,100.91 R90.2 ; P3.C12 v2(75.05,94.6)
  BOTTOM w0.203: v1(106.27,98.07) 105.96,97.76 76.82,97.76 75.18,96.13 75.18,95.05 75.05,94.92 v2(75.05,94.6)
AD9545_OUT1A_N: length 53.9
  TOP w0.203: P3.A7 v2(71.88,92.06)
  BOTTOM w0.203: v2(71.88,92.06) 71.88,92.38 71.73,92.53 71.73,93.17 72.62,94.06 72.62,98.3 74.32,100 98.37,100 99.47,101.09 99.47,103.91 100.63,105.08 104.7,105.08 106.04,106.43 106.04,111.4 105.66,111.79 103.07,111.79 R140.2
AD9545_OUT1A_P: length 50.9
  TOP w0.203: P3.A6 v2(71.24,92.06)
  BOTTOM w0.203: v2(71.24,92.06) 71.24,92.38 71.35,92.48 71.35,93.36 72.21,94.22 72.21,98.47 74.15,100.41 98.21,100.41 99.06,101.26 99.06,104.08 100.47,105.49 104.53,105.49 105.64,106.59 105.64,108.86 105.23,109.27 R217.2
AD9545_OUT1B_N: length 51.8
  TOP w0.203: R144.2 v1(107.19,110.08) ; P3.B11 v2(74.42,93.99)
  BOTTOM w0.203: v2(74.42,93.99) 74.42,94.31 74.29,94.44 74.29,97.21 75.87,98.78 105.59,98.78 107.16,100.36 107.16,103.76 109.45,106.05 109.45,108.19 108.5,109.14 107.39,109.14 107.19,109.35 v1(107.19,110.08)
AD9545_OUT1B_P: length 51.1
  TOP w0.203: P3.B10 v2(73.78,93.99) ; v1(107.19,107.8) R143.2
  BOTTOM w0.203: v1(107.19,107.8) 107.19,108.53 107.39,108.74 108.33,108.74 109.04,108.03 109.04,106.21 106.76,103.93 106.76,100.52 105.42,99.19 75.7,99.19 73.89,97.37 73.89,94.44 73.78,94.33 v2(73.78,93.99)
B_CAPVDD: length 18.8
  TOP w0.508: C69.1 112.46,39.46 v1(112.8,39.8) 113.56,40.56 ; C77.1 v1(113.16,36.42) 114.1,36.42
  TOP w0.61: 113.56,40.56 114.19,41.19 C68.1 ; C76.1 117.89,38.79 115.52,36.42 114.1,36.42
  TOP w0.762: C76.1 C68.1
  BOTTOM w0.305: U2.8 112.85,40.07 112.85,39.85 v1(112.8,39.8) ; v1(113.16,36.42) 113.21,36.37 113.21,36.13 U2.20
B_CFG0: length 5.8
  TOP w0.305: R156.1 114.17,44.91 v2(112.85,43.59)
  BOTTOM w0.203: U2.4 112.62,42.68 112.62,43.36 v2(112.85,43.59)
B_CKAN/CKDN/A3A/D1A: length 68.6
  TOP w0.108: P5.B19 v4(79.18,26.41)
  L3_SIG w0.102: v2(101.05,34.68) 101.05,34.42 98.13,31.5 93.53,31.5 92.94,30.9 92.94,19.75 92.66,19.47 91.6,19.47 91.5,19.57 91.5,21.63 91.22,21.91 90.76,21.91 90.48,21.63 90.48,19.57 90.38,19.47 90.18,19.47 90.08,19.57 90.08,21.63 89.8,21.91 89.34,21.91 89.06,21.63 89.06,19.57 88.96,19.47 88.76,19.47 88.66,19.57 88.66,21.63 88.38,21.91 87.92,21.91 87.64,21.63 87.64,19.57 87.54,19.47 87.33,19.47 87.23,19.57 87.23,21.63 86.95,21.91 86.5,21.91 86.22,21.63 86.22,19.57 86.12,19.47 85.91,19.47 85.81,19.57 85.81,21.63 85.53,21.91 85.07,21.91 84.79,21.63 84.79,19.57 84.69,19.47 83.78,19.47 79.7,23.55 79.7,23.7 79.91,23.91 79.91,24.05 79.77,24.2 79.62,24.2 79.41,23.98 79.27,23.98 79.02,24.23 79.02,26.25 v4(79.18,26.41)
  BOTTOM w0.108: U2.40 105.66,36.43 105.66,36.29 104.83,35.46 102.09,35.46 101.31,34.68 v2(101.05,34.68)
B_CKAP/CKDP/A2C/D0C: length 68.6
  TOP w0.108: P5.B18 v4(78.55,26.41)
  L3_SIG w0.102: v2(101.52,34.19) 101.26,34.19 98.25,31.19 93.66,31.19 93.24,30.78 93.24,19.62 92.79,19.17 91.48,19.17 91.2,19.45 91.2,21.5 91.09,21.61 90.89,21.61 90.79,21.5 90.79,19.45 90.51,19.17 90.05,19.17 89.77,19.45 89.77,21.5 89.67,21.61 89.47,21.61 89.37,21.5 89.37,19.45 89.09,19.17 88.63,19.17 88.35,19.45 88.35,21.5 88.25,21.61 88.05,21.61 87.94,21.5 87.94,19.45 87.66,19.17 87.21,19.17 86.93,19.45 86.93,21.5 86.83,21.61 86.62,21.61 86.52,21.5 86.52,19.45 86.24,19.17 85.79,19.17 85.51,19.45 85.51,21.5 85.4,21.61 85.2,21.61 85.1,21.5 85.1,19.45 84.82,19.17 83.65,19.17 78.71,24.11 78.71,26.24 v4(78.55,26.41)
  BOTTOM w0.108: v2(101.52,34.19) 101.52,34.46 102.22,35.15 104.96,35.15 105.88,36.07 106.01,36.07 U2.39
B_CKBN/CKEN/B1A/E1A: length 66
  TOP w0.108: v4(73.06,23.91) 73.25,24.1 73.84,24.1 74.89,25.15 74.89,25.77 P5.A12
  L3_SIG w0.102: v2(103.51,41.15) 103.25,41.15 103.07,41.33 103.07,47.33 101.88,48.52 79.38,48.52 71.98,41.13 71.98,24.53 72.41,24.1 72.87,24.1 v4(73.06,23.91)
  BOTTOM w0.108: U2.46 106.03,39.78 105.89,39.78 105.08,40.59 103.81,40.59 103.51,40.88 v2(103.51,41.15)
B_CKBP/CKEP/B0C/E0C: length 65.8
  TOP w0.108: P5.A11 74.58,25.77 74.58,25.28 73.71,24.41 73.25,24.41 v4(73.06,24.6)
  L3_SIG w0.102: v4(73.06,24.6) 72.87,24.41 72.53,24.41 72.29,24.65 72.29,29.56 72.39,29.66 72.71,29.66 72.81,29.76 72.81,29.97 72.71,30.07 72.39,30.07 72.29,30.17 72.29,30.37 72.39,30.47 72.71,30.47 72.81,30.58 72.81,30.78 72.71,30.88 72.39,30.88 72.29,30.98 72.29,41.01 79.5,48.22 101.76,48.22 102.77,47.21 102.77,41.21 103.03,40.94 v2(103.03,40.68)
  BOTTOM w0.108: U2.45 105.69,39.41 105.69,39.55 104.96,40.28 103.68,40.28 103.28,40.68 v2(103.03,40.68)
B_DA0N/DC0N/A0B/C0B: length 67.9
  TOP w0.108: v4(81.09,25.45) P5.A21
  L3_SIG w0.102: v4(81.09,25.45) 80.92,25.29 80.92,24.31 81.14,24.09 81.28,24.09 81.41,24.22 81.55,24.22 81.7,24.07 81.7,23.93 81.57,23.8 81.57,23.66 82.02,23.21 91.1,23.21 91.21,23.32 91.21,23.75 91.11,23.86 89.16,23.86 88.88,24.14 88.88,24.59 89.16,24.87 91.11,24.87 91.21,24.97 91.21,25.18 91.11,25.28 89.16,25.28 88.88,25.56 88.88,26.01 89.16,26.29 91.11,26.29 91.21,26.4 91.21,26.6 91.11,26.7 89.16,26.7 88.88,26.98 88.88,27.44 89.16,27.72 91.11,27.72 91.21,27.82 91.21,28.02 91.11,28.12 89.16,28.12 88.88,28.4 88.88,28.86 89.16,29.14 91.11,29.14 91.21,29.24 91.21,29.55 91.11,29.65 90.81,29.65 90.53,29.93 90.53,30.38 90.81,30.66 91.11,30.66 91.21,30.76 91.21,32 90.67,32.55 90.67,32.95 90.99,33.27 91.38,33.27 91.91,32.74 92.06,32.74 92.19,32.88 92.19,33.04 91.67,33.56 91.67,33.95 91.99,34.27 92.39,34.27 92.94,33.73 97.57,33.73 102.25,38.4 104.72,38.4 106.86,36.27 106.86,33.6 107.02,33.44 v2(107.27,33.44)
  BOTTOM w0.108: v2(107.27,33.44) 107.27,33.19 107.45,33 108.03,33 108.51,33.48 108.51,33.61 U2.32
B_DA0P/DC0P/A0A/C0A: length 68.1
  TOP w0.108: v4(80.45,25.45) P5.A20
  L3_SIG w0.102: v4(80.45,25.45) 80.62,25.28 80.62,24.18 81.9,22.91 91.23,22.91 91.52,23.2 91.52,23.88 91.24,24.16 89.29,24.16 89.18,24.26 89.18,24.47 89.29,24.57 91.24,24.57 91.52,24.85 91.52,25.3 91.24,25.58 89.29,25.58 89.18,25.68 89.18,25.89 89.29,25.99 91.24,25.99 91.52,26.27 91.52,26.73 91.24,27.01 89.29,27.01 89.18,27.11 89.18,27.31 89.29,27.41 91.24,27.41 91.52,27.69 91.52,28.15 91.24,28.43 89.29,28.43 89.18,28.53 89.18,28.73 89.29,28.83 91.24,28.83 91.52,29.11 91.52,29.67 91.24,29.95 90.94,29.95 90.84,30.05 90.84,30.26 90.94,30.36 91.24,30.36 91.52,30.64 91.52,32.13 90.97,32.68 90.97,32.82 91.11,32.96 91.26,32.96 91.79,32.44 92.18,32.44 92.5,32.75 92.5,33.16 91.98,33.68 91.98,33.83 92.12,33.97 92.26,33.97 92.81,33.42 97.7,33.42 102.37,38.1 104.6,38.1 106.55,36.14 106.55,33.47 106.81,33.22 v2(106.81,32.97)
  BOTTOM w0.108: v2(106.81,32.97) 107.06,32.97 107.33,32.7 108.16,32.7 108.76,33.3 108.9,33.3 U2.31
B_DA1N/DC1N/A1C/C1C: length 67.6
  TOP w0.108: P5.B16 v4(77.28,26.41)
  L3_SIG w0.102: v2(103.85,31.9) 103.85,31.9 103.85,31.63 103.3,31.09 103.3,30.11 104.19,29.22 104.19,19.71 102.08,17.6 101.94,17.6 101.54,18 101.14,18 100.82,17.68 100.82,17.28 101.22,16.88 101.22,16.74 101.08,16.59 100.93,16.59 100.53,17 100.14,17 99.81,16.67 99.81,16.28 100.22,15.88 100.22,15.73 99.99,15.51 98.51,15.51 98.41,15.61 98.41,16.06 98.13,16.34 97.68,16.34 97.4,16.06 97.4,15.61 97.3,15.51 97.09,15.51 96.99,15.61 96.99,16.06 96.71,16.34 96.25,16.34 95.97,16.06 95.97,15.61 95.87,15.51 95.67,15.51 95.57,15.61 95.57,16.06 95.29,16.34 94.83,16.34 94.55,16.06 94.55,15.61 94.45,15.51 94.25,15.51 94.15,15.61 94.15,16.06 93.87,16.34 93.41,16.34 93.13,16.06 93.13,15.61 93.03,15.51 92.83,15.51 92.72,15.61 92.72,16.06 92.44,16.34 91.99,16.34 91.71,16.06 91.71,15.61 91.61,15.51 91.4,15.51 91.3,15.61 91.3,16.06 91.02,16.34 90.57,16.34 90.29,16.06 90.29,15.61 90.18,15.51 89.98,15.51 89.88,15.61 89.88,16.06 89.6,16.34 89.14,16.34 88.86,16.06 88.86,15.61 88.76,15.51 85.34,15.51 83.97,16.87 81.99,16.87 77.09,21.77 77.09,21.91 77.31,22.13 77.31,22.27 77.17,22.42 77.02,22.42 76.8,22.2 76.66,22.2 76.15,22.71 76.15,24.73 77.11,25.7 77.11,26.25 v4(77.28,26.41)
  BOTTOM w0.108: U2.36 107.06,34.99 107.06,34.86 104.1,31.9 v2(103.85,31.9)
B_DA1P/DC1P/A1B/C1B: length 67.6
  TOP w0.108: P5.B15 v4(76.64,26.41)
  L3_SIG w0.102: v2(104.32,31.42) 104.06,31.42 103.6,30.96 103.6,30.23 104.49,29.34 104.49,19.58 102.21,17.3 101.81,17.3 101.41,17.7 101.27,17.7 101.13,17.55 101.13,17.41 101.53,17.01 101.53,16.61 101.2,16.29 100.81,16.29 100.41,16.69 100.26,16.69 100.12,16.55 100.12,16.4 100.52,16 100.52,15.61 100.12,15.2 98.39,15.2 98.11,15.48 98.11,15.93 98.01,16.04 97.8,16.04 97.7,15.93 97.7,15.48 97.42,15.2 96.97,15.2 96.69,15.48 96.69,15.93 96.58,16.04 96.38,16.04 96.28,15.93 96.28,15.48 96,15.2 95.54,15.2 95.26,15.48 95.26,15.93 95.16,16.04 94.96,16.04 94.86,15.93 94.86,15.48 94.58,15.2 94.12,15.2 93.84,15.48 93.84,15.93 93.74,16.04 93.54,16.04 93.43,15.93 93.43,15.48 93.15,15.2 92.7,15.2 92.42,15.48 92.42,15.93 92.32,16.04 92.11,16.04 92.01,15.93 92.01,15.48 91.73,15.2 91.28,15.2 91,15.48 91,15.93 90.89,16.04 90.69,16.04 90.59,15.93 90.59,15.48 90.31,15.2 89.85,15.2 89.57,15.48 89.57,15.93 89.47,16.04 89.27,16.04 89.17,15.93 89.17,15.48 88.89,15.2 85.21,15.2 83.85,16.56 81.86,16.56 75.84,22.58 75.84,24.85 76.81,25.82 76.81,26.24 v4(76.64,26.41)
  BOTTOM w0.108: v2(104.32,31.42) 104.32,31.68 107.28,34.65 107.42,34.65 U2.35
B_DA2N/DD0N/A2B/D0B: length 69.5
  TOP w0.108: v4(77.77,24.76) 77.52,24.76 76.8,25.48 76.8,25.77 P5.A15
  L3_SIG w0.102: v2(102.93,33.77) 102.93,33.52 101.22,31.81 101.22,29.98 102.79,28.4 102.79,26.1 102.17,25.48 102.17,22.68 101.87,22.38 101.72,22.38 100.09,24.01 99.69,24.01 99.37,23.69 99.37,23.3 101,21.66 101,21.52 100.86,21.38 100.72,21.38 99.08,23.01 98.69,23.01 98.36,22.69 98.36,22.29 100,20.66 100,20.51 99.85,20.37 99.71,20.37 98.08,22 97.68,22 97.36,21.68 97.36,21.28 98.99,19.65 98.99,19.51 98.85,19.36 98.7,19.36 97.07,21 96.68,21 96.35,20.67 96.35,20.28 97.99,18.65 97.99,18.5 97.57,18.09 83.05,18.09 78.53,22.61 78.53,22.76 78.67,22.89 78.67,23.04 78.52,23.18 78.38,23.18 78.24,23.04 78.1,23.04 77.77,23.37 v4(77.77,24.76)
  BOTTOM w0.108: U2.38 106.38,35.72 106.38,35.59 105.16,34.37 103.78,34.37 103.19,33.77 v2(102.93,33.77)
B_DA2P/DD0P/A2A/D0A: length 69.5
  TOP w0.108: v4(77.3,24.3) 77.3,24.54 76.49,25.35 76.49,25.77 P5.A14
  L3_SIG w0.102: v2(103.4,33.29) 103.13,33.29 101.52,31.68 101.52,30.1 103.1,28.53 103.1,25.97 102.47,25.35 102.47,22.56 101.99,22.08 101.6,22.08 99.96,23.71 99.82,23.71 99.68,23.57 99.68,23.42 101.31,21.79 101.31,21.39 100.99,21.07 100.59,21.07 98.96,22.7 98.81,22.7 98.67,22.56 98.67,22.42 100.3,20.78 100.3,20.39 99.98,20.06 99.58,20.06 97.95,21.7 97.81,21.7 97.66,21.55 97.66,21.41 99.3,19.78 99.3,19.38 98.97,19.06 98.58,19.06 96.95,20.69 96.8,20.69 96.66,20.55 96.66,20.4 98.29,18.77 98.29,18.38 97.7,17.78 82.93,17.78 77.46,23.25 77.46,24.13 v4(77.3,24.3)
  BOTTOM w0.108: U2.37 106.72,35.36 106.59,35.36 105.28,34.06 103.91,34.06 103.4,33.55 v2(103.4,33.29)
B_DA3N/DD1N/A3C/D1C: length 69
  TOP w0.108: P5.C12 v4(74.74,28.95)
  L3_SIG w0.102: v2(103.24,36.97) 103.23,36.71 103.23,36.71 105.87,34.06 105.87,18.74 100.96,13.83 94.84,13.83 94.74,13.73 94.74,13.34 94.46,13.06 94,13.06 93.72,13.34 93.72,13.73 93.62,13.83 84.56,13.83 82.98,15.41 80.98,15.41 73.8,22.58 73.8,25.47 73.32,25.95 73.32,27.95 73.91,28.54 74.33,28.54 v4(74.74,28.95)
  BOTTOM w0.108: U2.42 104.98,37.15 104.98,37.03 104.46,36.51 103.44,36.51 103.24,36.71 v2(103.24,36.97)
B_DA3P/DD1P/A3B/D1B: length 69.3
  TOP w0.108: v4(74.74,27.99) P5.C11
  L3_SIG w0.102: v4(74.74,27.99) 74.49,28.24 74.04,28.24 73.62,27.83 73.62,26.08 74.11,25.6 74.11,22.7 74.36,22.45 74.51,22.45 74.73,22.67 74.87,22.67 75.02,22.53 75.02,22.38 74.79,22.16 74.79,22.02 74.94,21.87 75.08,21.87 75.3,22.1 75.45,22.1 75.59,21.95 75.59,21.81 75.37,21.59 75.37,21.44 81.1,15.71 83.11,15.71 84.68,14.14 93.75,14.14 94.03,13.85 94.03,13.46 94.13,13.36 94.33,13.36 94.43,13.46 94.43,13.85 94.71,14.14 100.83,14.14 105.56,18.86 105.56,33.93 103.02,36.49 103.02,36.49 v2(102.75,36.5)
  BOTTOM w0.108: U2.41 105.34,36.8 105.19,36.8 104.58,36.2 103.32,36.2 103.02,36.5 v2(102.75,36.5)
B_DB0N/DE0N/B0B/E0B: length 65.6
  TOP w0.108: v4(82.68,25.48) 82.68,25.93 P5.A24
  L3_SIG w0.102: v2(100.15,39.06) 100.15,38.77 99.85,38.47 98.78,38.47 98.5,38.19 98.5,37.46 98.4,37.35 98.2,37.35 98.1,37.46 98.1,38.62 97.82,38.9 97.26,38.9 96.98,38.62 96.98,35.67 96.88,35.57 96.67,35.57 96.57,35.67 96.57,38.62 96.29,38.9 95.84,38.9 95.56,38.62 95.56,35.67 95.46,35.57 95.25,35.57 95.15,35.67 95.15,38.62 94.87,38.9 94.41,38.9 94.13,38.62 94.13,35.67 94.03,35.57 93.83,35.57 93.73,35.67 93.73,38.62 93.45,38.9 90.5,38.9 90.22,38.62 90.22,35.48 90.12,35.38 89.92,35.38 89.82,35.48 89.82,38.62 89.54,38.9 88.98,38.9 88.7,38.62 88.7,31.39 86.28,28.98 86.28,27.74 86.18,27.64 86.05,27.64 85.95,27.54 85.95,27.33 86.05,27.23 86.18,27.23 86.28,27.13 86.28,25.05 85.73,24.5 82.86,24.5 82.51,24.85 82.51,25.31 82.68,25.47 v4(82.68,25.48)
  BOTTOM w0.108: U2.44 105.35,39.04 105.22,39.04 104.88,39.38 100.75,39.38 100.44,39.06 v2(100.15,39.06)
B_DB0P/DE0P/B0A/E0A: length 65.4
  TOP w0.108: P5.A23 v4(82.04,25.48)
  L3_SIG w0.102: v4(82.04,25.48) 82.21,25.31 82.21,24.73 82.74,24.2 85.86,24.2 86.59,24.93 86.59,28.85 89,31.27 89,38.49 89.11,38.59 89.41,38.59 89.51,38.49 89.51,35.36 89.79,35.08 90.25,35.08 90.53,35.36 90.53,38.49 90.63,38.59 93.32,38.59 93.42,38.49 93.42,35.54 93.7,35.26 94.16,35.26 94.44,35.54 94.44,38.49 94.54,38.59 94.74,38.59 94.85,38.49 94.85,35.54 95.13,35.26 95.58,35.26 95.86,35.54 95.86,38.49 95.96,38.59 96.17,38.59 96.27,38.49 96.27,35.54 96.55,35.26 97,35.26 97.28,35.54 97.28,38.49 97.39,38.59 97.69,38.59 97.79,38.49 97.79,37.33 98.07,37.05 98.53,37.05 98.81,37.33 98.81,38.07 98.91,38.17 99.98,38.17 100.37,38.56 v2(100.65,38.56)
  BOTTOM w0.108: U2.43 105,38.68 105,38.82 104.75,39.07 100.88,39.07 100.65,38.85 v2(100.65,38.56)
B_DB1N/DE1N/B1C/E1C: length 67
  TOP w0.108: P5.D25 83.15,29.6 83.15,30.34 83.62,30.81 83.62,32.25 v4(83.79,32.41)
  L3_SIG w0.102: v4(83.79,32.41) 83.62,32.25 83.62,31.96 83.83,31.75 84.18,31.75 85.4,32.97 85.4,33.52 85.3,33.63 85.24,33.63 85.14,33.73 85.14,33.93 85.24,34.03 85.3,34.03 85.4,34.13 85.4,37.62 85.29,37.73 82.24,37.73 81.96,38.01 81.96,38.47 82.24,38.75 85.29,38.75 85.39,38.85 85.39,39.05 85.29,39.15 82.24,39.15 81.96,39.43 81.96,39.89 82.24,40.17 85.29,40.17 85.39,40.27 85.39,40.47 85.29,40.58 82.24,40.58 81.96,40.86 81.96,41.31 82.24,41.59 85.29,41.59 85.39,41.69 85.39,41.9 85.29,42 82.24,42 81.96,42.28 81.96,42.73 82.24,43.01 85.29,43.01 85.39,43.12 85.39,43.91 86.04,44.56 97.95,44.56 100.13,42.38 101.33,42.38 v2(101.51,42.55)
  BOTTOM w0.108: v2(101.51,42.55) 101.68,42.38 104.66,42.38 106.55,40.49 106.73,40.49 U2.48
B_DB1P/DE1P/B1B/E1B: length 67
  TOP w0.108: v4(83.15,32.41) 83.31,32.25 83.31,30.94 82.84,30.46 82.84,29.6 P5.D24
  L3_SIG w0.102: v2(101.51,41.89) 101.33,42.07 100,42.07 97.83,44.25 86.17,44.25 85.7,43.78 85.7,42.99 85.42,42.71 82.37,42.71 82.27,42.61 82.27,42.4 82.37,42.3 85.42,42.3 85.7,42.02 85.7,41.57 85.42,41.29 82.37,41.29 82.27,41.19 82.27,40.98 82.37,40.88 85.42,40.88 85.7,40.6 85.7,40.15 85.42,39.86 82.37,39.86 82.27,39.76 82.27,39.56 82.37,39.46 85.42,39.46 85.7,39.18 85.7,38.72 85.42,38.44 82.37,38.44 82.27,38.34 82.27,38.14 82.37,38.04 85.42,38.04 85.71,37.75 85.71,32.85 84.31,31.45 83.7,31.45 83.31,31.83 83.31,32.25 v4(83.15,32.41)
  BOTTOM w0.108: v2(101.51,41.89) 101.68,42.07 104.54,42.07 106.38,40.23 106.38,40.14 U2.47
B_DB2N/DF0N/B2B/F0B: length 67.6
  TOP w0.108: P5.C24 v4(82.99,28.95)
  L3_SIG w0.102: v2(101.64,45.48) 101.46,45.3 101.46,44.8 100.96,44.3 99.98,44.3 97.98,46.3 80.67,46.3 75.65,41.29 75.65,39.64 75.75,39.54 76.62,39.54 76.9,39.26 76.9,38.8 76.62,38.52 75.75,38.52 75.65,38.42 75.65,38.22 75.75,38.12 76.62,38.12 76.9,37.84 76.9,37.38 76.62,37.1 75.75,37.1 75.65,37 75.65,36.79 75.75,36.69 76.62,36.69 76.9,36.41 76.9,35.96 76.62,35.68 75.75,35.68 75.65,35.58 75.65,35.37 75.75,35.27 76.62,35.27 76.9,34.99 76.9,34.53 76.62,34.25 75.75,34.25 75.65,34.15 75.65,33.95 75.75,33.85 76.62,33.85 76.9,33.57 76.9,33.11 76.62,32.83 75.75,32.83 75.65,32.73 75.65,32.17 77.2,30.62 80.75,30.62 80.85,30.72 80.85,30.78 80.95,30.89 81.15,30.89 81.26,30.78 81.26,30.72 81.36,30.62 81.79,30.62 82.83,29.59 82.83,29.12 v4(82.99,28.95)
  BOTTOM w0.108: v2(101.64,45.48) 101.46,45.3 101.46,44.82 102.14,44.15 104.35,44.15 107.3,41.2 107.44,41.2 U2.50
B_DB2P/DF0P/B2A/F0A: length 67.6
  TOP w0.108: P5.C23 v4(82.36,28.95)
  L3_SIG w0.102: v2(100.97,45.49) 101.16,45.3 101.16,44.93 100.84,44.6 100.11,44.6 98.11,46.6 80.54,46.6 75.35,41.41 75.35,39.51 75.63,39.23 76.5,39.23 76.6,39.13 76.6,38.93 76.5,38.83 75.63,38.83 75.35,38.55 75.35,38.09 75.63,37.81 76.5,37.81 76.6,37.71 76.6,37.51 76.5,37.4 75.63,37.4 75.35,37.12 75.35,36.67 75.63,36.39 76.5,36.39 76.6,36.29 76.6,36.08 76.5,35.98 75.63,35.98 75.35,35.7 75.35,35.25 75.63,34.97 76.5,34.97 76.6,34.86 76.6,34.66 76.5,34.56 75.63,34.56 75.35,34.28 75.35,33.82 75.63,33.54 76.5,33.54 76.6,33.44 76.6,33.24 76.5,33.14 75.63,33.14 75.35,32.86 75.35,32.04 77.08,30.32 81.67,30.32 82.52,29.46 82.52,29.12 v4(82.36,28.95)
  BOTTOM w0.108: v2(100.97,45.49) 101.16,45.3 101.16,44.69 102.01,43.84 104.22,43.84 107.09,40.98 107.09,40.84 U2.49
B_DB3N/DF1N/B3C/F1C: length 64.7
  TOP w0.108: v4(84.58,25.53) 84.58,25.54 P5.A27
  L3_SIG w0.102: v2(107.25,43.42) 107.25,43.19 107.63,42.81 107.63,41.36 105.49,39.22 101.82,39.22 100.52,40.52 98.09,40.52 97.81,40.8 97.81,41.61 97.71,41.71 97.5,41.71 97.4,41.61 97.4,40.8 97.12,40.52 96.67,40.52 96.39,40.8 96.39,42.31 96.28,42.41 96.08,42.41 95.98,42.31 95.98,40.8 95.7,40.52 95.24,40.52 94.96,40.8 94.96,42.31 94.86,42.41 94.66,42.41 94.56,42.31 94.56,40.8 94.28,40.52 93.82,40.52 93.54,40.8 93.54,42.31 93.44,42.41 93.24,42.41 93.13,42.31 93.13,40.8 92.85,40.52 92.4,40.52 92.12,40.8 92.12,42.31 92.02,42.41 91.81,42.41 91.71,42.31 91.71,40.8 91.43,40.52 90.98,40.52 90.7,40.8 90.7,42.31 90.59,42.41 90.39,42.41 90.29,42.31 90.29,40.8 90.01,40.52 89.55,40.52 89.27,40.8 89.27,42.31 89.17,42.41 88.97,42.41 88.87,42.31 88.87,40.8 88.59,40.52 87.96,40.52 87.32,39.88 87.32,32.02 84.73,29.44 84.73,26.13 84.58,25.97 v4(84.58,25.53)
  BOTTOM w0.108: U2.54 108.84,42.62 108.71,42.62 108.33,43 107.42,43 107.25,43.17 v2(107.25,43.42)
B_DB3P/DF1P/B3B/F1B: length 64.6
  TOP w0.108: P5.A26 v4(83.94,25.54)
  L3_SIG w0.102: v2(106.77,42.95) 107.06,42.95 107.33,42.68 107.33,41.49 105.36,39.52 101.95,39.52 100.64,40.82 98.21,40.82 98.11,40.92 98.11,41.73 97.83,42.01 97.38,42.01 97.1,41.73 97.1,40.92 97,40.82 96.79,40.82 96.69,40.92 96.69,42.44 96.41,42.72 95.95,42.72 95.67,42.44 95.67,40.92 95.57,40.82 95.37,40.82 95.27,40.92 95.27,42.44 94.99,42.72 94.53,42.72 94.25,42.44 94.25,40.92 94.15,40.82 93.95,40.82 93.85,40.92 93.85,42.44 93.57,42.72 93.11,42.72 92.83,42.44 92.83,40.92 92.73,40.82 92.52,40.82 92.42,40.92 92.42,42.44 92.14,42.72 91.69,42.72 91.41,42.44 91.41,40.92 91.31,40.82 91.1,40.82 91,40.92 91,42.44 90.72,42.72 90.26,42.72 89.98,42.44 89.98,40.92 89.88,40.82 89.68,40.82 89.58,40.92 89.58,42.44 89.3,42.72 88.84,42.72 88.56,42.44 88.56,40.92 88.46,40.82 87.83,40.82 87.02,40.01 87.02,32.15 84.43,29.56 84.43,26.25 84.27,26.1 84.27,25.86 v4(83.94,25.54)
  BOTTOM w0.108: v2(106.77,42.95) 107.04,42.95 107.29,42.7 108.2,42.7 108.48,42.41 108.48,42.27 U2.53
B_GMSL-PWDNB: length 42
  TOP w0.203: P5.B48 v2(98.23,27.37)
  TOP w0.356: R187.1 114.17,49.26 v1(112.84,49.26)
  L3_SIG w0.356: v1(112.84,49.26) 114.93,47.17 v2(114.93,40.04)
  L8_SIG w0.203: v2(114.93,40.04) 114.73,39.83 114.73,39.17 115.87,38.02 115.87,30.58 115.22,29.93 106.32,29.93 104.57,28.18 98.77,28.18 98.23,27.65 v2(98.23,27.37)
  BOTTOM w0.203: U2.11 v2(114.93,40.04)
B_MFP0/LMN0/FSYNC: length 38.1
  TOP w0.203: v2(99.5,25.45) P5.A50
  L8_SIG w0.203: v2(111.51,44.86) 109.97,46.4 105.17,46.4 103.38,44.61 99.51,44.61 98.34,43.44 98.34,31.92 97.06,30.64 97.06,26.8 97.88,25.98 99.25,25.98 99.5,25.73 v2(99.5,25.45)
  BOTTOM w0.203: v2(111.51,44.86) 111.25,44.61 111.25,43.43 U2.1
B_MFP1/LMN1/VS0/DE0/HS0: length 38.3
  TOP w0.203: v2(100.14,25.45) P5.A51
  L8_SIG w0.203: v2(111.96,44.43) 111.96,44.42 111.73,44.2 111.4,44.2 109.61,45.98 105.34,45.98 103.56,44.21 99.69,44.21 98.74,43.26 98.74,31.74 97.42,30.41 97.42,26.94 98.02,26.34 99.5,26.34 100.14,25.7 v2(100.14,25.45)
  BOTTOM w0.203: U2.2 111.71,43.18 111.71,44.18 v2(111.96,44.43)
B_MFP2/LMN2: length 38.2
  TOP w0.203: v2(100.77,25.45) P5.A52
  L8_SIG w0.203: v2(112.4,44) 112.4,43.99 112.17,43.76 111.25,43.76 109.44,45.58 105.51,45.58 103.73,43.8 99.86,43.8 99.15,43.09 99.15,31.56 97.78,30.19 97.78,27.09 98.17,26.7 99.84,26.7 100.77,25.76 v2(100.77,25.45)
  BOTTOM w0.203: v2(112.4,44) 112.17,43.77 112.17,42.93 U2.3
B_MFP3/LMN3/VS1/DE1/HS1: length 30.7
  TOP w0.203: P5.B49 v2(98.87,27.37)
  L8_SIG w0.203: v2(98.87,27.37) 98.87,27.63 99.07,27.83 104.76,27.83 106.46,29.52 115.43,29.52 116.28,30.38 116.28,38.22 115.27,39.23 115.27,39.67 v2(115.55,39.95)
  BOTTOM w0.203: U2.12 v2(115.55,39.95)
B_MFP4/LOCK: length 29.6
  TOP w0.203: P5.B50 v2(99.5,27.37)
  L8_SIG w0.203: v2(99.5,27.37) 104.86,27.37 106.61,29.12 115.78,29.12 116.71,30.05 116.71,38.43 v2(115.73,39.42)
  BOTTOM w0.203: U2.13 v2(115.73,39.42)
B_MFP5/ERRB: length 33.4
  TOP w0.203: P5.C48 v2(98.23,28.95)
  L8_SIG w0.203: v2(116.89,40.16) 116,41.05 114.53,41.05 113.84,40.36 113.84,38.84 114.86,37.82 114.86,32.16 114.08,31.37 106.05,31.37 104.83,30.15 99.19,30.15 98.23,29.2 v2(98.23,28.95)
  BOTTOM w0.203: U2.14 116.69,39.67 116.69,39.95 v2(116.89,40.16)
B_MFP6/CFG1: length 20.3
  TOP w0.203: P5.C50 v2(99.5,28.95)
  TOP w0.356: v2(113.06,30.87) 113.06,30.54 112.51,30 R186.1
  L8_SIG w0.203: v2(113.06,30.87) 106.12,30.87 105.03,29.77 99.97,29.77 99.5,29.3 v2(99.5,28.95)
  BOTTOM w0.203: U2.25 113.06,32.75 v2(113.06,30.87)
B_MFP7: length 30.5
  TOP w0.203: P5.D48 v2(98.23,29.91) ; R173.2 v1(120.63,25.83)
  BOTTOM w0.203: v1(120.63,25.83) 117.65,25.83 116.83,25.01 116.83,23.69 115.47,22.33 108.05,22.33 104.93,25.45 104.93,28.04 103.4,29.57 98.58,29.57 v2(98.23,29.91)
B_MFP7/SDA1_RX1: length 13.5
  TOP w0.203: U25.2 118.92,24.91 R175.2 R173.1 119.03,27 113.83,32.21 v2(112.52,32.21)
  BOTTOM w0.203: v2(112.52,32.21) 112.52,32.58 U2.26
B_MFP8: length 32.1
  TOP w0.203: R174.2 v1(117.41,26.56) ; v2(96.85,32.33) 96.64,32.13 P5.D46
  BOTTOM w0.203: v1(117.41,26.56) 116.31,25.46 116.31,23.94 115.27,22.9 108.18,22.9 105.39,25.7 105.39,28.24 103.61,30.02 99.16,30.02 v2(96.85,32.33)
B_MFP8/SCL1_TX1: length 13.1
  TOP w0.203: v2(111.91,32.21) 111.91,31.88 112.12,31.67 113.63,31.67 118.31,27 R174.1 R158.2 118.42,24.9 U25.3
  BOTTOM w0.203: v2(111.91,32.21) 111.91,32.48 U2.27
B_SCL: length 59
  TOP w0.203: R137.2 140.91,60.91 v2(140.49,60.91) 140.2,60.62 U19.11
  L8_SIG w0.203: v2(111.79,28.54) 112.13,28.54 112.23,28.65 119.38,28.65 119.71,28.98 119.71,39.69 133.73,53.71 133.73,55.3 135.69,57.25 139.14,57.25 139.98,58.09 139.98,60.4 v2(140.49,60.91)
  BOTTOM w0.203: v2(111.79,28.54) 111.79,30.99 109.9,32.87 U2.29
B_SDA: length 59.5
  TOP w0.203: R138.2 140.91,59.92 v2(140.49,59.92) 140.28,60.12 U19.10
  L8_SIG w0.203: v2(140.49,59.92) 140.49,58.02 139.31,56.85 135.86,56.85 134.14,55.13 134.14,53.44 120.18,39.48 120.18,28.81 119.61,28.24 112.52,28.24 112.21,27.94 v2(111.74,27.94)
  BOTTOM w0.203: U2.28 111.18,32.51 111.18,32.21 112.31,31.07 112.31,28.21 112.05,27.94 v2(111.74,27.94)
